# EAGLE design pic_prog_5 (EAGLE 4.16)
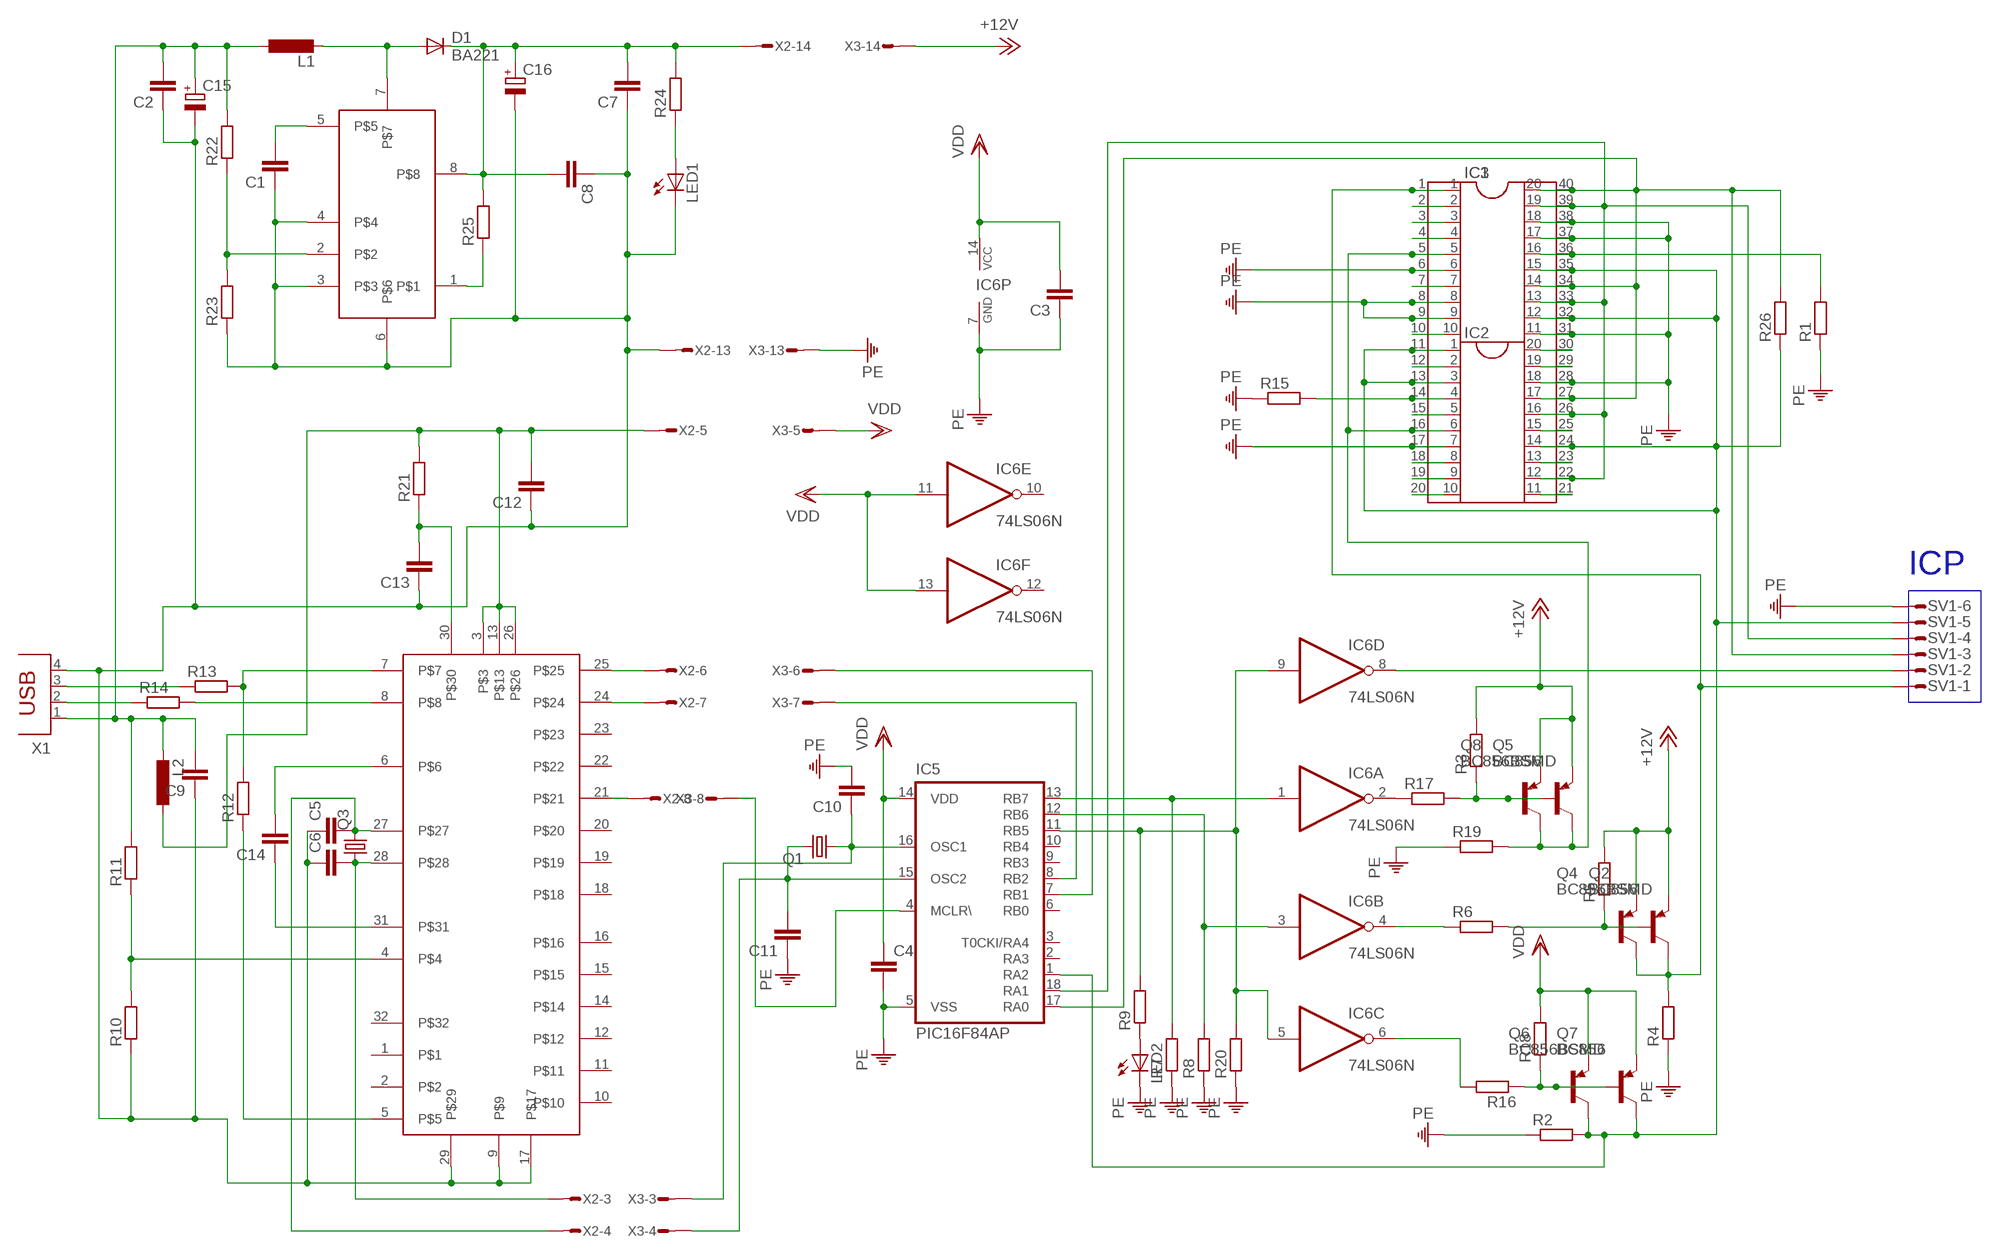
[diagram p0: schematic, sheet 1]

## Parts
C1  C-EUC1206  [C1206]
C2  C-EUC1206  [C1206]
C3  C-EU050-024X044  [C050-024X044]
C4  C-EUC1206  [C1206]
C5  C-EUC1206  [C1206]
C6  C-EUC1206  [C1206]
C7  C-EUC1206  [C1206]
C8  C-EUC1206  [C1206]
C9  C-EUC1206  [C1206]
C10  C-EUC1206  [C1206]
C11  C-EUC1206  [C1206]
C12  C-EUC1206  [C1206]
C13  C-EUC1206  [C1206]
C14  C-EUC1206  [C1206]
C15  CPOL-EUSMCD  [SMC_D]
C16  CPOL-EUSMCD  [SMC_D]
D1  BA221  [DO35-10]
IC1  DIL20  [DIL20]
IC2  DIL20  [DIL20]
IC3  DIL40  [DIL40]
IC5  PIC16F84AP  [DIL18]
IC6  74LS06N  [DIL14]
L1  L-EU2200-15.24  [2200-15.24]
L2  L-EU2200-15.24  [2200-15.24]
LED1  LED3MM  [LED3MM]
LED2  LED3MM  [LED3MM]
Q1  CRYSTALHC49U-H  [HC49U-H]
Q2  BC856  [TO92L]
Q3  CRYSTALHC49U-H  [HC49U-H]
Q4  BC856BSMD  [SOT23-BEC]
Q5  BC856  [TO92L]
Q6  BC856BSMD  [SOT23-BEC]
Q7  BC856  [TO92L]
Q8  BC856BSMD  [SOT23-BEC]
R1  R-EU_0207/10  [0207/10]
R2  R-EU_0207/10  [0207/10]
R3  R-EU_0207/10  [0207/10]
R4  R-EU_0207/10  [0207/10]
R5  R-EU_0207/10  [0207/10]
R6  R-EU_0207/10  [0207/10]
R7  R-EU_0207/10  [0207/10]
R8  R-EU_0207/10  [0207/10]
R9  R-EU_0207/10  [0207/10]
R10  R-EU_R1206  [R1206]
R11  R-EU_R1206  [R1206]
R12  R-EU_R1206  [R1206]
R13  R-EU_R1206  [R1206]
R14  R-EU_R1206  [R1206]
R15  R-EU_0207/10  [0207/10]
R16  R-EU_0207/10  [0207/10]
R17  R-EU_0207/10  [0207/10]
R18  R-EU_0207/10  [0207/10]
R19  R-EU_0207/10  [0207/10]
R20  R-EU_0207/10  [0207/10]
R21  R-EU_R1206  [R1206]
R22  R-EU_R1206  [R1206]
R23  R-EU_R1206  [R1206]
R24  R-EU_R1206  [R1206]
R25  R-EU_R1206  [R1206]
R26  R-EU_0207/10  [0207/10]
SV1  MT6-6Y.  [6_1]
U$1  FT232  [TQFP32-08]
U$2  MAX761  [DIL08]
X1  PN61729  [PN61729]
X2  MICROMATCH-20/  [PLS]
X3  MICROMATCH-20\\  [PBS]

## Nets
+12V: Q2.1(E) Q4.E Q5.1(E) Q8.E R3.2 R5.2 X3.P$14
N$1: IC1.1 IC3.1 Q2.3(C) Q4.C R4.2 SV1.P$1
N$2: IC1.2 IC3.2
N$3: IC1.3 IC3.3
N$4: IC1.4 IC3.4
N$5: C1.2 U$2.5
N$6: IC6.8(D:O) SV1.P$2
N$7: IC1.7 IC3.7
N$8: C11.2 IC5.15(OSC2) Q1.2 X3.P$4
N$9: R22.1 R23.2 U$2.2
N$10: IC1.10 IC3.10
N$12: IC2.2 IC3.12
N$13: IC5.4(MCLR\) X3.P$8
N$14: IC2.4 IC3.14 R15.2
N$15: IC2.5 IC3.15
N$16: C2.2 C9.2 C15.+ L1.1 L2.2 R11.2 R22.2 X1.1
N$18: IC2.8 IC3.18
N$19: IC2.9 IC3.19
N$20: IC2.10 IC3.20
N$21: IC2.11 IC3.21
N$22: IC1.13 IC1.19 IC2.12 IC2.16 IC3.22 IC3.26 IC3.33 IC3.39 IC5.18(RA1) SV1.P$4
N$23: IC2.13 IC3.23
N$24: IC1.12 IC1.15 IC2.1 IC2.3 IC2.14 IC3.11 IC3.13 IC3.24 IC3.32 IC3.35 IC5.1(RA2) Q6.C Q7.3(C) R2.2 R26.1 SV1.P$5
N$25: IC2.15 IC3.25
N$26: IC1.16 IC3.36 R1.2
N$29: IC2.19 IC3.29
N$30: IC2.20 IC3.30
N$31: D1.A L1.2 U$2.7
N$32: C10.1 IC5.16(OSC1) Q1.1 X3.P$3
N$33: IC1.14 IC1.20 IC2.17 IC3.27 IC3.34 IC3.40 IC5.17(RA0) R26.2 SV1.P$3
N$34: C7.2 C8.2 C16.+ D1.C R24.2 R25.2 U$2.8 X2.P$14
N$35: LED1.A R24.1
N$36: C12.2 L2.1 R21.2 U$1.3 U$1.13 U$1.26 X2.P$5
N$37: R25.1 U$2.1
N$38: U$1.25 X2.P$6
N$39: U$1.21 X2.P$8
N$40: U$1.24 X2.P$7
N$41: C14.2 U$1.6
N$42: C14.1 U$1.31
N$43: R14.1 X1.2
N$44: R14.2 U$1.8
N$45: R13.1 X1.3
N$46: R12.2 R13.2 U$1.7
N$47: R12.1 U$1.5
N$48: C6.2 Q3.1 U$1.28 X2.P$3
N$49: R10.2 R11.1 U$1.4
N$50: C1.1 C2.1 C5.1 C6.1 C7.1 C8.1 C9.1 C12.1 C13.1 C15.- C16.- LED1.K(C) R10.1 R23.1 U$1.9 U$1.17 U$1.29 U$2.3 U$2.4 U$2.6 X1.4 X2.P$13
N$51: C13.2 R21.1 U$1.30
N$52: IC5.7(RB1) X3.P$6
N$53: IC5.8(RB2) X3.P$7
N$56: Q6.B Q7.2(B) R16.1 R18.1
N$58: IC5.11(RB5) IC6.5(C:I) IC6.9(D:I) R9.2 R20.2
N$59: LED2.A R9.1
N$60: IC5.12(RB6) IC6.3(B:I) R8.2
N$61: IC5.13(RB7) IC6.1(A:I) R7.2
N$62: IC6.6(C:O) R16.2
N$63: IC6.2(A:O) R17.1
N$64: Q5.2(B) Q8.B R3.1 R17.2
N$66: IC1.5 IC2.6 IC3.5 IC3.16 Q5.3(C) Q8.C R19.2
N$67: IC6.4(B:O) R6.1
N$68: Q2.2(B) Q4.B R5.1 R6.2
N$69: C5.2 Q3.2 U$1.27 X2.P$4
PE: C3.1 C4.2 C10.2 C11.1 IC1.6 IC1.8 IC1.9 IC1.11 IC1.17 IC1.18 IC2.7 IC2.18 IC3.6 IC3.8 IC3.9 IC3.17 IC3.28 IC3.31 IC3.37 IC3.38 IC5.5(VSS) IC6.7(P:GND) LED2.K(C) R1.1 R2.1 R4.1 R7.1 R8.1 R15.1 R19.1 R20.1 SV1.P$6 X3.P$13
VDD: C3.2 C4.1 IC5.14(VDD) IC6.11(E:I) IC6.13(F:I) IC6.14(P:VCC) Q6.E Q7.1(E) R18.2 X3.P$5
Unconnected: IC5.2(RA3) IC5.3(T0CKI/RA4) IC5.6(RB0) IC5.9(RB3) IC5.10(RB4) IC6.10(E:O) IC6.12(F:O) U$1.1 U$1.2 U$1.10 U$1.11 U$1.12 U$1.14 U$1.15 U$1.16 U$1.18 U$1.19 U$1.20 U$1.22 U$1.23 U$1.32 X2.P$1 X2.P$2 X2.P$9 X2.P$10 X2.P$11 X2.P$12 X2.P$15 X2.P$16 X2.P$17 X2.P$18 X2.P$19 X2.P$20 X3.P$1 X3.P$2 X3.P$9 X3.P$10 X3.P$11 X3.P$12 X3.P$15 X3.P$16 X3.P$17 X3.P$18 X3.P$19 X3.P$20

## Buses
B$1

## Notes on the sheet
- ICP

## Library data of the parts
C1-C14 = rcl:C-EU: CAPACITOR, European symbol
C15 C16 = rcl:CPOL-EU: POLARIZED CAPACITOR, European symbol
D1 = diode:BA221: DIODE
IC1 IC2 = dil:DIL20: SOCKET DIL20
IC3 = dil:DIL40: SOCKET DIL40
IC5 = microchip:PIC16F8*: MICROCONTROLLER 8-Bit PIC16F8X Family - CMOS Flash/EEPROM Pin Compatible : PIC16F83, PIC16CR83, PIC16F84A, PIC16CR84 see also PIC16C*
IC6 = 74xx-eu:74*06: Hex INVERTER, open collector high-voltage output
L1 L2 = rcl:L-EU: INDUCTOR, European symbol
LED1 LED2 = led:LED: LED
Q1 Q3 = crystal:CRYSTAL: CRYSTAL
Q2 Q4-Q8 = transistor-pnp:BC856*: PNP Transistror
R1-R26 = rcl:R-EU_: RESISTOR, European symbol
SV1 = con-amp-mt:MT6-6Y: AMP MT6 CONNECTOR
U$1 = atmel:FT232
U$2 = maxim:MAX761
X1 = con-berg:PN61729: BERG USB connector
X2 X3 = con-amp-micromatch:MICROMATCH-20: MicroMaTch 20 9-215464-0 / 2-215464-0 Drawing Number C-215464 DDEController.pdf

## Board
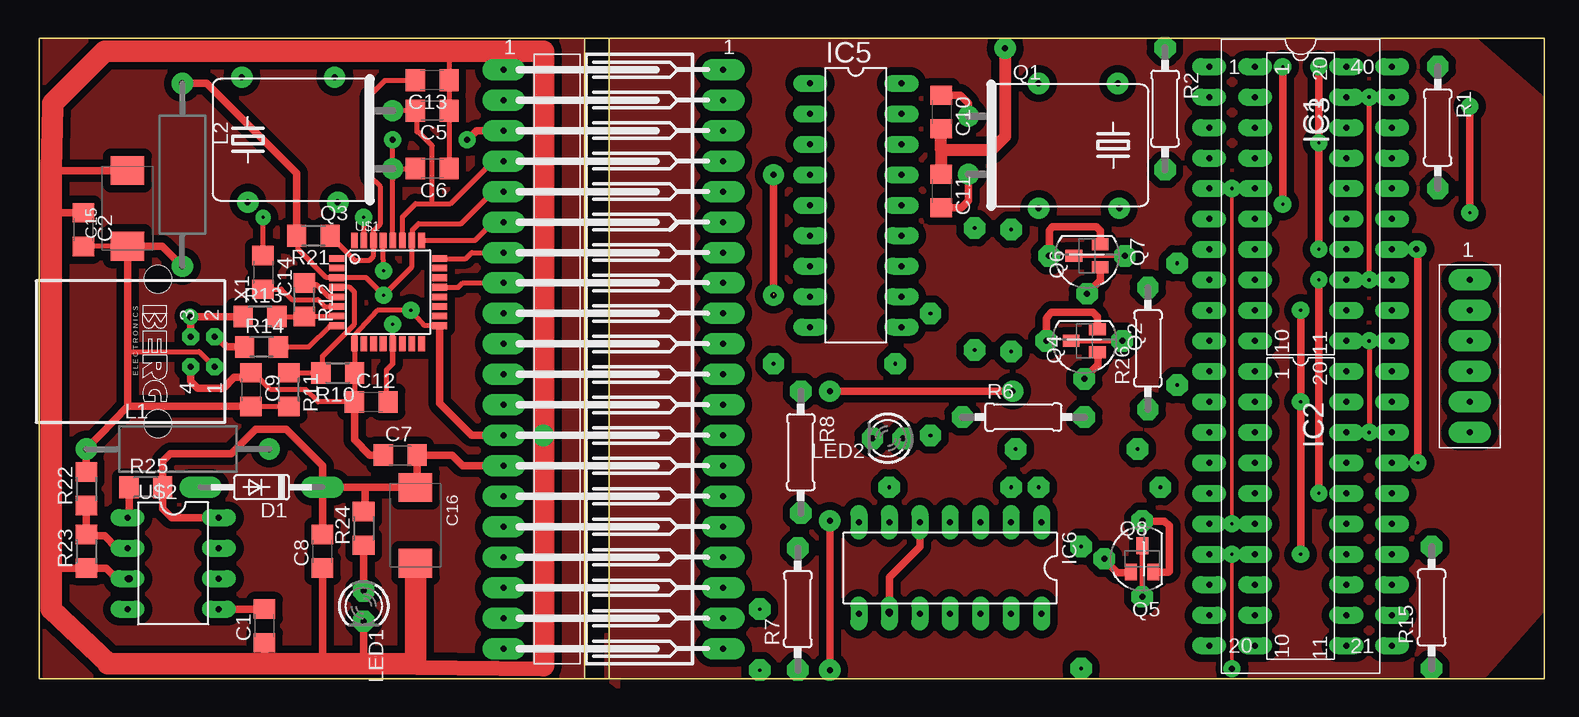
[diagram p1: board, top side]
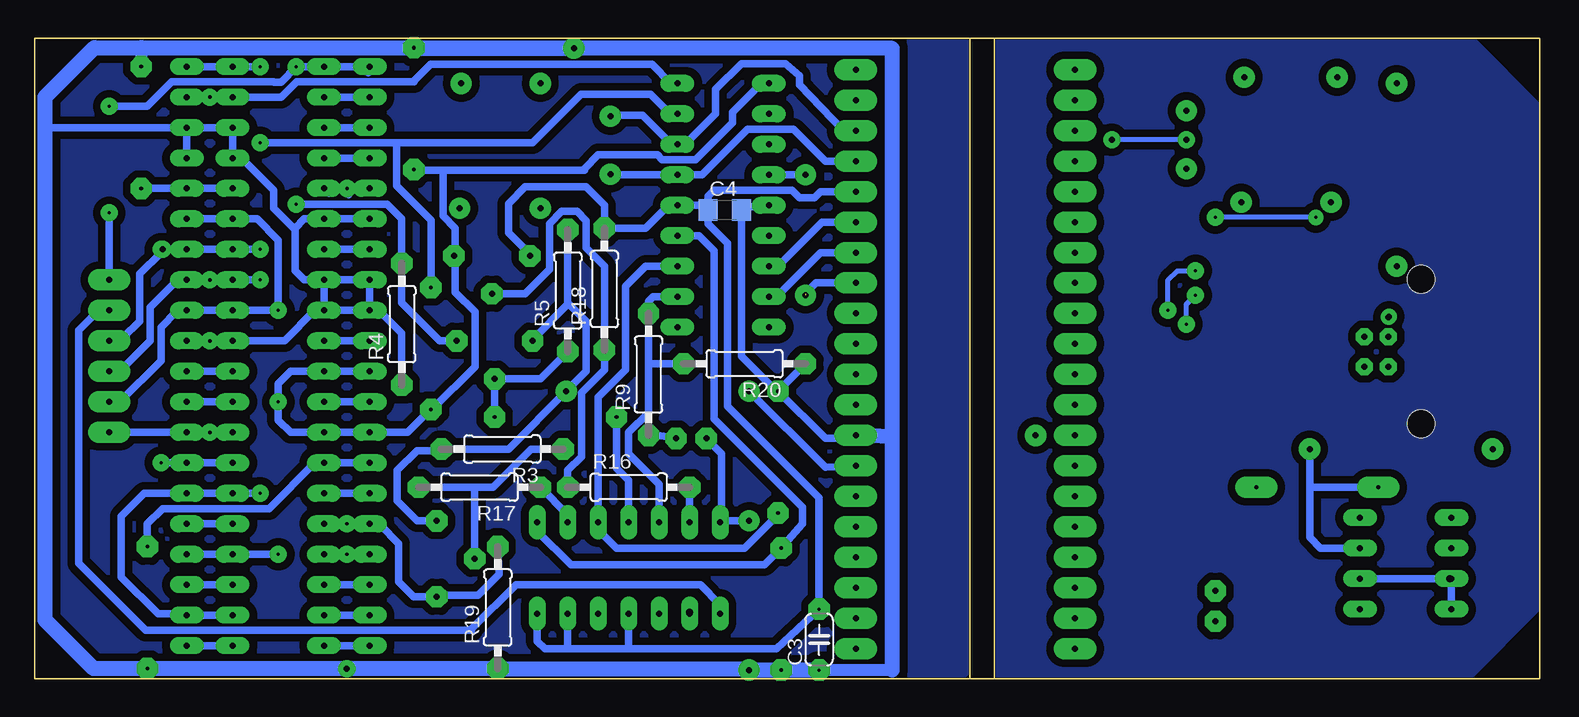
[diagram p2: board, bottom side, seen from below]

Size 125.46 x 53.39 mm. Coordinates in mm from the lower left corner, seen from the top.
Outline: 45.46,53.3 45.46,0.09
Outline: 47.49,0.09 47.49,53.3
Outline: 0,0 125.46,0 125.46,53.39 0,53.39 0,0
Copper layers (1*16): Top 0.035mm / dielectric 1.5mm / Bottom 0.035mm
Design rules "default": minimum track width 10mil, minimum drill 1mil, track to track 25mil, track to pad 25mil, pad to pad 25mil, via to via 8mil, smd to smd 8mil, copper to edge 1mil, drill to drill 10mil, minimum pad ring 10mil, minimum via ring 8mil, stop-mask expansion 4mil, vias tented up to drill 0mil, thermal gap 10mil

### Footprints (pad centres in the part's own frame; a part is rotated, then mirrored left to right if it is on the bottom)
C1206 = smd 1.6 x 1.8: 1 -1.4,0; 2 1.4,0
C050-024X044 = drill 0.254 pad 1.778 octagon: 1 -2.54,0; 2 2.54,0
SMC_D = smd 2.4 x 2.8: + -3.15,0; - 3.15,0
DO35-10 = drill 0.305 pad 1.778 long: A 5.08,0; C -5.08,0
DIL20 = drill 0.5 pad 1.422 long: 1 -11.43,-3.81; 2 -8.89,-3.81; 3 -6.35,-3.81; 4 -3.81,-3.81; 5 -1.27,-3.81; 6 1.27,-3.81; 7 3.81,-3.81; 8 6.35,-3.81; 9 8.89,-3.81; 10 11.43,-3.81; 11 11.43,3.81; 12 8.89,3.81; 13 6.35,3.81; 14 3.81,3.81; 15 1.27,3.81; 16 -1.27,3.81; 17 -3.81,3.81; 18 -6.35,3.81; 19 -8.89,3.81; 20 -11.43,3.81
DIL40 = drill 0.5 pad 1.422 long: 1 -24.13,-7.62; 2 -21.59,-7.62; 3 -19.05,-7.62; 4 -16.51,-7.62; 5 -13.97,-7.62; 6 -11.43,-7.62; 7 -8.89,-7.62; 8 -6.35,-7.62; 9 -3.81,-7.62; 10 -1.27,-7.62; 11 1.27,-7.62; 12 3.81,-7.62; 13 6.35,-7.62; 14 8.89,-7.62; 15 11.43,-7.62; 16 13.97,-7.62; 17 16.51,-7.62; 18 19.05,-7.62; 19 21.59,-7.62; 20 24.13,-7.62; 21 24.13,7.62; 22 21.59,7.62; 23 19.05,7.62; 24 16.51,7.62; 25 13.97,7.62; 26 11.43,7.62; 27 8.89,7.62; 28 6.35,7.62; 29 3.81,7.62; 30 1.27,7.62; 31 -1.27,7.62; 32 -3.81,7.62; 33 -6.35,7.62; 34 -8.89,7.62; 35 -11.43,7.62; 36 -13.97,7.62; 37 -16.51,7.62; 38 -19.05,7.62; 39 -21.59,7.62; 40 -24.13,7.62
DIL18 = drill 0.5 pad 1.422 long: 1 -10.16,-3.81; 2 -7.62,-3.81; 3 -5.08,-3.81; 4 -2.54,-3.81; 5 0,-3.81; 6 2.54,-3.81; 7 5.08,-3.81; 8 7.62,-3.81; 9 10.16,-3.81; 10 10.16,3.81; 11 7.62,3.81; 12 5.08,3.81; 13 2.54,3.81; 14 0,3.81; 15 -2.54,3.81; 16 -5.08,3.81; 17 -7.62,3.81; 18 -10.16,3.81
DIL14 = drill 0.5 pad 1.422 long: 1 -7.62,-3.81; 2 -5.08,-3.81; 3 -2.54,-3.81; 4 0,-3.81; 5 2.54,-3.81; 6 5.08,-3.81; 7 7.62,-3.81; 8 7.62,3.81; 9 5.08,3.81; 10 2.54,3.81; 11 0,3.81; 12 -2.54,3.81; 13 -5.08,3.81; 14 -7.62,3.81
2200-15.24 = drill 0.5 pad 1.778 round: 1 -7.62,0; 2 7.62,0
LED3MM = drill 0.5 pad 1.778 octagon: A -1.27,0; K 1.27,0
HC49U-H = drill 0.5 pad 1.778 round: 1 -2.413,-5.08; 2 2.413,-5.08
TO92L = drill 0.5 pad 1.778 octagon: 1 0,-3.162; 2 3.162,0; 3 0,3.162
SOT23-BEC = smd 1 x 1.4: B -0.95,-1.1; C 0,1.1; E 0.95,-1.1
0207/10 = drill 0.305 pad 1.778 octagon: 1 -5.08,0; 2 5.08,0
R1206 = smd 1.6 x 1.8: 1 -1.4,0; 2 1.4,0
6_1 = drill 0.5 pad 1.778 long: P$1 0,6.35; P$2 0,3.81; P$3 0,1.27; P$4 0,-1.27; P$5 0,-3.81; P$6 0,-6.35
TQFP32-08 = smd 1.27 x 0.559: 1 -4.293,2.8; 2 -4.293,2; 3 -4.293,1.2; 4 -4.293,0.4; 5 -4.293,-0.4; 6 -4.293,-1.2; 7 -4.293,-2; 8 -4.293,-2.8; 17 4.293,-2.8; 18 4.293,-2; 19 4.293,-1.2; 20 4.293,-0.4; 21 4.293,0.4; 22 4.293,1.2; 23 4.293,2; 24 4.293,2.8 | smd 0.559 x 1.27: 9 -2.8,-4.293; 10 -2,-4.293; 11 -1.2,-4.293; 12 -0.4,-4.293; 13 0.4,-4.293; 14 1.2,-4.293; 15 2,-4.293; 16 2.8,-4.293; 25 2.8,4.293; 26 2,4.293; 27 1.2,4.293; 28 0.4,4.293; 29 -0.4,4.293; 30 -1.2,4.293; 31 -2,4.293; 32 -2.8,4.293
DIL08 = drill 0.5 pad 1.422 long: 1 -3.81,-3.81; 2 -1.27,-3.81; 3 1.27,-3.81; 4 3.81,-3.81; 5 3.81,3.81; 6 1.27,3.81; 7 -1.27,3.81; 8 -3.81,3.81
PN61729 = drill 0.5 pad 1.422 octagon: 1 1.25,4.71; 2 -1.25,4.71; 3 -1.25,2.71; 4 1.25,2.71 | hole 2.3: -6.02,0; 6.02,0
PLS = drill 0.5 pad 1.778 long: P$1 0,24.13; P$2 0,21.59; P$3 0,19.05; P$4 0,16.51; P$5 0,13.97; P$6 0,11.43; P$7 0,8.89; P$8 0,6.35; P$9 0,3.81; P$10 0,1.27; P$11 0,-1.27; P$12 0,-3.81; P$13 0,-6.35; P$14 0,-8.89; P$15 0,-11.43; P$16 0,-13.97; P$17 0,-16.51; P$18 0,-19.05; P$19 0,-21.59; P$20 0,-24.13
PBS = drill 0.5 pad 1.778 long: P$1 5.08,24.13; P$2 5.08,21.59; P$3 5.08,19.05; P$4 5.08,16.51; P$5 5.08,13.97; P$6 5.08,11.43; P$7 5.08,8.89; P$8 5.08,6.35; P$9 5.08,3.81; P$10 5.08,1.27; P$11 5.08,-1.27; P$12 5.08,-3.81; P$13 5.08,-6.35; P$14 5.08,-8.89; P$15 5.08,-11.43; P$16 5.08,-13.97; P$17 5.08,-16.51; P$18 5.08,-19.05; P$19 5.08,-21.59; P$20 5.08,-24.13

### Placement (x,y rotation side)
C1  18.79,4.41 90 top
C2  3.68,37.43 270 top
C3  60.07,3.26 90 bottom
C4  67.94,39.08 0 bottom
C5  32.76,47.33 180 top
C6  32.76,42.51 180 top
C7  30.09,18.63 0 top
C8  23.62,10.63 90 top
C9  17.65,24.09 270 top
C10  75.2,47.23 270 top
C11  75.2,40.65 270 top
C12  27.68,23.08 0 top
C13  32.76,49.87 180 top
C14  18.66,33.87 270 top
C15  7.36,39.21 90 top
C16  31.36,12.79 270 top
D1  18.54,15.96 180 top
IC1  105.15,39.59 270 top
IC2  105.15,14.19 270 top
IC3  105.15,26.89 270 top
IC5  68.07,39.46 270 top
IC6  75.94,9.23 180 top
L1  11.55,19.14 0 top
L2  11.93,42 270 top
LED1  27.05,6.06 270 top
LED2  70.73,20.03 180 top
Q1  82.55,44.46 270 top
Q2  87.12,28.16 270 top
Q3  24.38,44.92 90 top
Q4  87.12,28.16 90 top
Q5  91.94,10 180 top
Q6  87.35,35.24 90 top
Q7  87.35,35.24 270 top
Q8  91.94,10 0 top
R1  116.58,45.94 270 top
R2  93.85,47.51 270 top
R3  86.48,19.14 180 bottom
R4  94.86,29.55 90 bottom
R5  81.02,32.35 90 bottom
R6  82.04,21.81 0 top
R7  63.24,5.8 90 top
R8  63.5,18.88 270 top
R9  74.29,25.36 90 bottom
R10  24.89,25.49 180 top
R11  20.82,24.09 270 top
R12  22.09,31.59 270 top
R13  18.41,30.19 0 top
R14  18.54,27.65 0 top
R15  116.07,5.93 90 top
R16  75.94,15.96 0 bottom
R17  88.39,15.96 180 bottom
R18  77.97,32.47 90 bottom
R19  86.86,5.93 90 bottom
R20  66.29,26.25 180 bottom
R21  22.86,36.92 180 top
R22  3.93,15.84 90 top
R23  3.93,10.63 90 top
R24  27.05,12.54 90 top
R25  8.89,15.96 0 top
R26  92.43,27.52 90 top
SV1  119.25,26.89 0 top
U$1  29.08,32.22 0 top
U$2  11.17,9.61 270 top
U$3  [REPER_3]  1.27,52.16 0 top
U$4  [REPER_3]  1.27,1.23 0 top
U$5  [REPER_3]  124.2,1.23 0 top
U$6  [REPER_3]  124.2,52.16 0 top
X1  9.9,27.27 270 top
X2  38.73,26.63 0 top
X3  51.94,26.63 0 top

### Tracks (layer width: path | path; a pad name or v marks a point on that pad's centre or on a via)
+12V  (via drill 0.5 pad 1.78)
  Top 0.406: 91.94,13.04 Q5.1 92.03,13.16 92.05,13.14 | Q2.1 83.95,28.17 83.92,28.21 | 94.2,8.98 94.12,8.89
  Top 0.61: v65.91,23.97 v81.15,23.97 | 94.12,8.89 Q8.E | 94.2,8.98 94.2,12.74 93.8,13.14 92.05,13.14 | 88.26,29.3 88.34,29.22 Q4.E 88.22,30.16 87.83,30.54 84.4,30.54 84.07,30.21 84.07,30.19 83.94,30.06 83.94,28.16 Q2.1
  Bottom 0.61: 86.99,19.14 91.31,19.14 91.44,19.27 R3.2 91.69,19.14 91.82,19.01 93.59,19.01 95.25,17.36 95.25,14.82 93.58,13.16 Q5.1 | 86.99,19.14 86.86,19.14 | 81.02,31.2 80.89,31.2 79.5,29.81 79.5,25.62 v81.15,23.97 85.97,19.14 86.99,19.14 | 81.02,31.2 R5.2 | Q2.1 83.95,28.27 81.02,31.2 | X3.P$14 59.56,17.62 v65.91,23.97
N$1  (via drill 0.25 pad 1.42)
  Top 0.254: v103.65,51.02 103.7,50.97 103.65,50.91
  Top 0.406: 90.32,28.16 Q2.3 Q4.C
  Top 0.61: v119.25,47.71 v119.25,38.82 | v103.65,39.56 103.65,50.91
  Bottom 0.61: 97.66,50.51 IC3.1 IC1.1 103.55,51.02 103.6,50.97 v103.65,51.02 103.65,50.99 104.92,49.72 105.51,49.72 105.53,49.75 114.04,49.75 116.07,47.71 v119.25,47.71 | 119.25,33.49 119.38,33.36 SV1.P$1 v119.25,38.82 | 103.6,39.59 103.63,39.56 v103.65,39.56 96.08,39.56 94.86,38.34 R4.2 94.86,31.33 91.69,28.16 Q2.3
N$2
  Bottom 0.61: IC3.2 IC1.2
N$3
  Bottom 0.61: IC1.3 101.21,45.81 101.09,45.94 IC3.3
N$4
  Bottom 0.61: IC1.4 101.21,43.4 101.09,43.27 100.96,43.4 IC3.4
N$5
  Top 0.61: C1.2 | C1.2 U$2.5 | C1.2 18.92,5.68
N$6
  Bottom 0.61: SV1.P$2 119.25,30.44 120.14,30.7 121.79,29.05 121.79,9.61 116.2,4.03 89.02,4.03 89.02,4.15 85.34,7.84 69.97,7.84 68.32,6.19 IC6.8
N$7
  Bottom 0.61: IC3.7 IC1.7
N$8
  Top 0.61: 77.36,41.52 77.39,41.54 Q1.2 77.47,39.84 76.88,39.25 C11.2
  Bottom 0.61: Q1.2 77.47,42 IC5.15 69.84,42 66.03,45.81 62.23,45.81 59.56,43.14 X3.P$4
N$9
  Top 0.61: R22.1 R23.2 4.06,11.9 5.46,11.9 6.48,10.88 7.23,10.88 U$2.2
N$10
  Bottom 0.61: IC1.10 101.34,28.28 101.21,28.16 IC3.10
N$11  (via drill 0.5 pad 1.78)
  other vias: 24.63,50.13
N$12
  Bottom 0.61: IC3.12 IC2.2
N$13  (via drill 0.5 pad 1.78)  (1 unrouted)
  Top 0.61: v61.21,31.97 v61.21,42
  Bottom 0.61: IC5.4 64.13,41.87 | IC5.4 64.26,41.87 | X3.P$8 60.32,32.98 61.21,32.09 | IC5.4 64.13,42.13 | v61.21,42 IC5.4
N$14
  Bottom 0.61: IC3.14 IC2.4 102.1,18 105.91,14.19 114.8,14.19 116.07,12.92 R15.2
N$15
  Bottom 0.61: IC3.15 IC2.5
N$16
  Top 0.406: C2.2 3.68,36.16 3.78,36.05 C15.+ | R11.2 20.7,22.69 20.7,22.7 20.69,22.69 C9.2 | X1.1 14.58,26.02 13.33,27.27 7.36,27.27
  Top 0.61: R22.2 L1.1 7.36,22.7 | C9.2 7.36,22.7 | L2.2 10.26,36.05 C15.+ 7.36,27.27 7.36,22.7
N$17  (via drill 0.5 pad 1.78)
  other vias: 24.89,39.71
N$18
  Bottom 0.61: IC2.8 101.21,7.84 101.09,7.96 100.96,7.84 IC3.18
N$19
  Bottom 0.61: IC3.19 IC2.9
N$20
  Bottom 0.61: IC3.20 IC2.10
N$21
  Bottom 0.61: IC2.11 IC3.21
N$22  (via drill 0.25 pad 1.42, 0.3 pad 1.42)
  Top 0.406: v110.87,33.24 v110.87,48.48
  Top 0.61: v106.67,15.46 v106.67,33.24
  Bottom 0.61: IC2.12 IC3.22 112.9,5.42 115.18,5.42 118.23,8.47 118.23,13.55 116.33,15.46 IC3.26 | IC3.39 v110.87,48.48 IC1.19 104.9,48.48 103.63,49.75 93.9,49.75 | IC3.26 113.03,15.46 | IC3.26 IC2.16 v106.67,15.46 | v106.67,33.24 IC1.13 v110.87,33.24 IC3.33 113.53,33.24 115.82,30.95 115.82,28.16 118.36,25.62 SV1.P$4 | SV1.P$4 120.52,25.49 | SV1.P$4 120.26,25.62 | 93.9,49.75 93.85,49.75 | IC5.18 72.44,49.62 74.01,51.19 92.45,51.19 93.9,49.75
N$23
  Bottom 0.61: IC2.13 IC3.23
N$24  (via drill 0.25 pad 1.42)
  Top 0.406: Q7.3 90.51,35.23 90.47,35.19 Q6.C
  Top 0.61: v105.15,30.7 v105.15,23.08 v105.15,10.38
  Bottom 0.61: 113.03,10.38 IC3.24 IC2.14 v105.15,10.38 | IC3.11 IC2.1 104.14,25.62 105.15,24.6 v105.15,23.08 105.15,21.55 104.14,20.54 IC2.3 IC3.13 94.36,20.54 92.45,22.44 R26.1 92.32,22.44 88.77,26 88.77,30.57 90.42,32.22 90.42,35.15 Q7.3 90.42,35.33 90.42,37.55 91.44,38.57 91.44,42.38 | IC3.35 113.03,38.32 | IC3.35 IC1.15 | IC3.35 106.93,38.32 105.15,36.54 v105.15,30.7 IC1.12 IC3.32 113.66,30.7 113.66,30.57 114.93,29.3 114.93,26.51 118.36,23.08 SV1.P$5 119.38,23.2 | R2.2 93.21,42.38 91.44,42.38 | 91.44,42.38 79.62,42.38 79.62,42.51 78.48,43.65 73.53,43.65 73.15,43.27 70.35,43.27 67.31,46.32 67.31,47.21 64.89,49.62 IC5.1
N$25
  Bottom 0.61: 112.9,12.92 IC3.25 IC2.15
N$26
  Bottom 0.61: IC1.16 IC3.36 116.33,40.86 116.45,40.73 R1.2
N$27  (via drill 0.5 pad 1.78)
  other vias: 17.39,39.71
N$28  (via drill 0.5 pad 1.78)
  other vias: 16.89,50.13
N$29
  Bottom 0.61: IC2.19 IC3.29
N$30
  Bottom 0.61: 112.9,25.62 IC3.30 | IC2.20 112.9,25.62 | 112.9,25.62 113.03,25.74
N$31
  Bottom 0.61: 19.17,15.96 L1.2 | 19.17,15.96 D1.A | U$2.7 18.28,10.88 19.17,11.77 19.17,15.96
N$32
  Top 0.61: 77.41,46.29 77.47,46.34 Q1.1 77.54,46.37 | C10.1 76.8,48.63 77.47,47.97 77.47,46.44 77.54,46.37 | 77.54,46.37 77.59,46.32
  Bottom 0.61: IC5.16 72.54,44.54 | IC5.16 72.38,44.54 74.8,46.95 77.39,46.95 Q1.1 | IC5.16 71.75,44.41 71.37,44.41 68.7,47.08 68.7,49.11 66.54,51.27 62.86,51.27 61.72,50.25 61.72,49.49 58.03,45.68 X3.P$3
N$33  (via drill 0.25 pad 1.42, 0.5 pad 1.42)
  Top 0.254: v114.8,35.78 v114.93,35.78
  Top 0.61: v106.67,51.02 v106.67,44.67 v106.67,35.78 | v114.93,35.78 v114.93,18
  Bottom 0.61: v106.67,44.67 106.29,44.54 106.17,44.67 95.42,44.67 | v106.67,51.02 IC1.20 IC3.40 | IC3.27 112.9,18 | IC3.27 IC2.17 | v106.67,35.78 IC1.14 IC3.34 v114.8,35.78 | v114.93,18 IC3.27 | v114.93,35.78 114.93,35.52 116.71,33.74 116.71,29.81 118.11,28.41 118.11,28.42 118.11,28.51 | SV1.P$3 120.39,28.28 118.11,28.51 | 118.11,28.51 117.85,28.54 | R26.2 92.43,38.21 95.3,41.09 95.3,44.51 95.32,44.54 95.37,44.54 95.37,44.59 95.42,44.64 95.42,44.67 | IC5.17 72.49,47.08 74.11,48.71 79.9,48.71 83.94,44.67 87.62,44.67 | 87.62,44.67 95.42,44.67 | 87.62,44.67 87.37,44.67
N$34
  Top 0.61: D1.C 23.62,17.74 20.57,20.79 18.03,20.79 16,18.76 10.92,18.76 10.29,18.13 R25.2 | D1.C 27.17,15.96 | C8.2 D1.C | R25.2 10.29,15.84 10.28,15.84 | R25.2 10.29,14.18 11.04,13.42 14.85,13.42 14.98,13.55 U$2.8 | R24.2 27.17,13.94 27.17,15.96 | 31.49,15.96 31.49,15.94 C16.+ | 27.17,15.96 31.49,15.96 | 31.49,15.96 C7.2 34.41,18.63 35.3,17.74 X2.P$14
N$35
  Top 0.61: LED1.A R24.1
N$36  (via drill 0.25 pad 1.42)
  Top 0.406: U$1.13 29.48,26.27 28.95,25.74 28.95,23.71 | U$1.13 29.48,29.53 v29.46,29.55 | U$1.3 24.82,33.42 | U$1.3 27.24,33.42 v28.7,31.97 31.08,34.35 U$1.26 31.11,36.55 31.11,37.43 31.62,37.94 35.17,37.94 37.84,40.6 X2.P$5 38.98,40.6 | 24.69,33.42 24.63,33.36 | U$1.3 24.69,33.42 | 24.69,33.42 23.94,33.42 21.59,35.78 21.59,36.92 R21.2 | U$1.13 29.48,26.25
  Top 0.61: 28.95,23.71 29.08,23.58 C12.2 | R21.2 21.46,38.95 21.46,42.13 13.96,49.62 L2.1
  Bottom 0.406: v28.7,31.97 29.46,31.2 v29.46,29.55
N$37
  Top 0.61: U$2.1 7.49,13.42 7.49,13.43 R25.1
N$38
  Top 0.406: X2.P$6 37.84,38.06 36.32,36.54 31.87,36.54 U$1.25
N$39
  Top 0.406: U$1.21 34.94,32.62 35.3,32.98 X2.P$8
N$40
  Top 0.406: U$1.24 35.56,35.02 36.06,35.52 40.13,35.52 40.25,35.65 X2.P$7
N$41
  Top 0.406: U$1.6 23.8,31.02 23.24,31.59 21.08,31.59 20.19,32.47 18.79,32.47 C14.2
N$42  (via drill 0.25 pad 1.27, 0.25 pad 1.42)
  Top 0.406: C14.1 v18.66,38.44 | U$1.31 27.05,36.54 v27.05,38.44
  Bottom 0.406: v18.66,38.44 v27.05,38.44
N$43
  Top 0.61: X1.2 14.75,28.52 15.62,27.65 R14.1
N$44
  Top 0.406: U$1.8 24.25,29.42 22.47,27.65 R14.2
N$45  (via drill 0.5 pad 1.27)
  Top 0.61: X1.3 v12.61,30.15 | R13.1 | v12.57,30.19 R13.1 | R13.1 17.14,30.06
  Bottom 0.61: v12.61,30.15 v12.57,30.19
N$46
  Top 0.406: U$1.7 22.25,30.22 22.22,30.19 R12.2 20.06,30.19 R13.2
N$47
  Top 0.406: U$1.5 24.14,31.82 23.11,32.86 22.22,32.86 R12.1
N$48  (via drill 0.5 pad 1.42)
  Top 0.406: Q3.1 29.46,41.62 29.48,41.6 U$1.28 | Q3.1 C6.2 | Q3.1 v29.46,44.92
  Top 0.61: X2.P$3 36.44,45.68 v35.68,44.92
  Bottom 0.406: v29.46,44.92 v35.68,44.92
N$49
  Top 0.406: U$1.4 25.88,32.62 26.28,32.22 26.28,29.55 23.62,26.89 23.62,25.62 R10.2 R11.1
N$50  (via drill 0.25 pad 1.42, 0.5 pad 1.78, 0.6)
  Top 0.406: 32.13,29.42 U$1.17 33.27,29.42 33.27,29.43 32.13,29.43 v30.98,30.7 28.19,30.7 26.28,28.66 U$1.9 R10.1 C12.1 | U$1.29 28.68,34.91 28.7,34.89 v28.7,34 28.68,34.02 | 1.01,42.38 1.27,42.38 1.29,42.36 | C12.1 | C12.1 23.24,23.08 22.22,24.09 19.3,24.09 18.03,25.36 17.78,25.36 | C6.1 C5.1 34.16,49.74 34.16,49.75 C13.1 34.16,51.65 34.16,52.29
  Top 0.61: U$2.4 7.36,5.68 | C2.1 1.01,38.83 1.01,38.82 | C9.1 17.65,25.36 17.52,25.23 | 17.78,25.36 C9.1 | 1.29,42.36 C15.- | 18.79,1.23 C1.1 | 29.46,1.23 29.46,1.1 27.05,1.23 LED1.K | C8.1 23.62,1.23 | 1.01,9.11 1.01,9.23 R23.1 5.59,9.23 6.47,8.34 v7.49,8.34 U$2.3 | X1.4 12.61,24.81 13.2,24.22 15.36,24.22 16.25,25.11 17.52,25.11 17.65,25.23 C9.1 | U$1.17 33.37,29.2 33.4,29.17 33.4,22.95 36.06,20.28 X2.P$13 v42.03,20.28 | C12.1 26.28,19.9 27.55,18.63 C7.1 | 41.78,0.85 42.03,1.1
  Top 1.27: 31.36,1.23 31.36,0.98 41.78,0.85
  Top 1.778: 18.92,1.23 23.62,1.23 27.05,1.23 29.46,1.23 31.36,1.23 C16.- | 42.03,1.1 v42.03,20.28 42.03,52.29 34.16,52.29 5.46,52.29 1.14,47.97 1.14,47.71 1.01,42.38 1.01,38.82 1.01,9.11 1.01,5.8 5.8,1.25 | 18.92,1.23 18.79,1.23 | 18.92,1.23 5.71,1.23
  Bottom 0.406: v28.7,34 30.22,34 30.98,33.24 v30.98,30.7
  Bottom 0.61: v7.49,8.34 U$2.6 | U$2.3 U$2.4
N$51
  Top 0.406: R21.1 26.29,34.89 27.55,34.89 27.88,35.21 U$1.30 27.88,37.37 28.44,37.94 28.44,40.98 27.55,41.87 27.55,48.6 28.82,49.87 C13.2
N$52
  Bottom 0.61: 64.31,34.38 IC5.7 63.5,34.38 59.81,38.06 X3.P$6
N$53
  Bottom 0.61: X3.P$7 59.94,35.52 63.62,31.84 IC5.8
N$54  (via drill 0.5 pad 1.78)
  other vias: 83.31,39.21
N$55  (via drill 0.5 pad 1.78)
  other vias: 90.04,39.21
N$56
  Top 0.61: Q7.2 87.35,32.09 88.45,33.19 Q6.B
  Bottom 0.61: 81.02,16.09 R16.1 81.02,17.36 79.88,18.5 79.88,23.84 77.97,25.74 R18.1 77.97,34.38 79.5,35.9 79.5,38.19 80.26,38.95 81.53,38.95 82.55,37.94 82.55,34.12 84.58,32.09 87.37,32.09 Q7.2
N$57  (via drill 0.5 pad 1.78)
  other vias: 83.31,49.62
N$58  (via drill 0.6)
  Top 0.61: v70.86,5.55 70.86,8.47 73.4,11.01 IC6.5
  Bottom 0.61: IC6.5 73.4,16.22 75.94,18.76 75.94,20.54 74.29,22.19 74.29,26.25 | 74.29,26.25 R9.2 74.29,31.46 73.91,31.84 IC5.11 | IC6.9 v70.86,5.55 | 74.29,26.25 R20.2
N$59
  Bottom 0.61: R9.1 74.29,20.41 LED2.A
N$60
  Bottom 0.61: IC6.3 78.35,13.04 78.48,12.92 | IC6.3 78.48,23.46 76.19,25.74 76.19,32.73 74.54,34.38 IC5.12 | R8.2 63.62,13.81 63.62,13.55 66.29,10.88 76.96,10.88 78.48,12.41 IC6.3
N$61
  Bottom 0.61: IC5.13 70.1,36.92 68.83,35.65 68.83,21.68 61.46,14.31 61.46,12.92 R7.2 64.64,9.49 80.77,9.49 83.56,12.28 IC6.1 83.56,13.17
N$62
  Bottom 0.61: IC6.6 R16.2
N$63
  Bottom 0.61: IC6.2 81.02,13.68 R17.1
N$64
  Top 0.406: 91.05,8.85 91.01,8.89 Q8.B | 88.77,9.97 88.78,9.98 Q5.2
  Top 0.61: 91.05,8.85 89.89,8.85 88.77,9.97
  Bottom 0.61: 93.59,15.96 R17.2 88.77,15.96 | 88.77,15.96 88.77,15.84 88.78,15.82 Q5.2 | R3.1 84.07,19.14 87.24,15.96 88.77,15.96
N$65  (via drill 0.5 pad 1.78)
  other vias: 89.91,49.62
N$66  (via drill 0.25 pad 1.42)
  Top 0.305: v99.44,12.92 v99.41,40.86
  Top 0.406: 92.06,6.83 92.07,6.82 | Q5.3 92.06,6.83 | Q8.C 91.94,6.95 92.06,6.83
  Bottom 0.61: R19.2 86.74,8.72 88.51,6.95 91.56,6.95 91.82,6.69 91.94,6.82 Q5.3 93.86,6.83 95.12,8.09 95.12,11.27 96.64,12.79 97.28,12.79 97.53,13.04 IC3.16 v99.44,12.92 IC2.6 | v99.41,40.86 99.31,40.35 | v99.41,40.86 IC3.5 | IC1.5 100.96,40.48 100.83,40.86 v99.41,40.86
N$67
  Bottom 0.61: IC6.4 75.94,16.52 76.96,17.54 R6.1
N$68
  Top 0.406: Q2.2 87.12,24.98
  Top 0.61: 88.39,27.01 88.34,27.06 Q4.B 88.34,27.1 88.26,27.01 88.26,26.15 Q2.2
  Bottom 0.61: 87.12,24.98 R6.2 | 87.12,24.98 Q2.2 | R5.1 83.31,24.98 87.12,24.98
N$69
  Top 0.406: U$1.27 30.28,38.5 31.36,39.59 32.76,39.59 | C5.2 31.24,47.33 | C5.2 Q3.2 | C5.2 31.49,47.33 31.49,45.55 31.62,45.55 32.76,44.41 32.76,39.59 | X2.P$4 37.84,43.14 34.29,39.59 32.76,39.59
N$70
  pour Bottom: 45.22,53.15 5.46,53.15 0.2,47.89 0.2,5.78 5.88,0.1 45.3,0.1 45.44,0.24 45.44,53.15 45.36,53.23 45.02,53.23
N$71
  pour Bottom: 47.98,53.12 120.45,53.11 125.26,48.31 125.26,5.09 120.4,0.24 47.99,0.24 47.79,0.44 47.79,53.09 47.85,53.15
N$72
  pour Top: 0.5,53.18 45.21,53.18 45.21,0.22 0.5,0.22
N$73
  pour Top: 47.57,53.07 47.29,0.03 48.26,-0.66 48.27,53.07
N$74
  pour Top: 47.35,0.3 120.56,0.34 125.45,5.88 125.47,48.2 119.63,53.3 47.63,53.3
PE  (via drill 0.25 pad 1.42, 0.3 pad 1.42, 0.5 pad 1.42, 0.5 pad 1.78)
  Top 0.305: v99.44,0.85 v99.44,10.38
  Top 0.406: v110.87,28.16 v110.87,20.54
  Top 0.61: v65.91,0.72 v65.91,13.17
  Top 1.016: C10.2 75.18,45.83 75.18,44.03 | C11.1 75.18,42.05 75.18,44.03 | 75.18,44.03 79.37,44.03 80.51,45.17 v80.51,52.54
  Bottom 0.61: IC3.38 IC3.37 | IC3.38 IC1.18 IC1.17 | IC2.18 v110.87,20.54 IC3.28 SV1.P$6 | IC3.31 v110.87,28.16 IC1.11 104.64,28.16 102.1,30.7 IC1.9 | 124.58,45.94 IC3.38 | IC1.9 97.78,30.7 | 101.21,10.38 101.34,10.25 IC2.7 101.34,10.5 101.21,10.38 | IC3.17 v99.44,10.38 101.21,10.38 | IC1.17 109.09,43.4 | IC3.6 IC1.6 102.99,38.32 103.75,37.55 103.75,37.43 | IC1.8 101.47,33.11 101.34,32.98 IC1.9 | 97.78,30.7 IC3.9 96.77,30.7 94.86,28.79 R4.1 | 97.78,30.7 97.53,30.95 IC3.8 IC1.8 | IC1.8 101.47,33.36 | IC1.17 108.2,43.4 105.53,40.73 105.53,39.21 103.75,37.43 | 103.75,37.43 103.75,34 102.99,33.24 IC1.8 | v65.91,13.17 68.19,13.17 | 68.19,13.17 IC6.7 | LED2.K 68.19,18.76 68.19,13.17 | X3.P$13 56.89,20.03 59.56,20.03 R8.1 | R8.1 63.88,24.22 66.54,26.89 66.54,39.33 | R8.1 R20.1 | v65.91,0.72 65.96,0.78 | 86.86,0.78 R19.1 | 66.54,39.33 66.54,39.46 C4.2 66.54,39.33 | IC5.5 64.38,39.33 66.54,39.33
  Bottom 1.016: 53.97,0.72 C3.1 | 116.58,52.59 R1.1
  Bottom 1.27: 86.99,1.1 R19.1 v99.44,0.85 R15.1 120.54,0.85 124.58,4.89 124.58,45.94 124.58,48.49 120.48,52.59 116.58,52.59 R2.1 93.72,52.59 93.72,52.54 v80.51,52.54 | 53.97,0.72 53.97,20.16 | 53.97,20.16 53.97,52.54 93.85,52.54 | 53.97,20.16 X3.P$13 | C3.1 R7.1 v65.91,0.72 | 65.96,0.78 86.86,0.78
VDD
  Top 0.61: 84.2,35.27 Q7.1 84.2,37.38 84.47,37.66 88.13,37.66 88.45,37.34 Q6.E
  Bottom 0.61: 83.69,5.42 IC6.14 83.56,3.14 82.93,2.5 81.02,2.5 | 75.94,2.5 IC6.11 | 81.02,2.5 IC6.13 | Q7.1 84.18,35.38 85.97,37.17 85.97,39.59 84.58,40.98 79.5,40.98 77.97,39.46 R18.2 74.54,37.55 72.64,39.46 IC5.14 69.21,39.46 69.21,39.21 C4.1 | 75.94,2.5 81.02,2.5 | 75.94,2.5 63.62,2.5 C3.2 60.07,15.08 67.69,22.7 67.69,36.28 69.34,37.94 69.34,39.21 | 69.34,39.21 C4.1 | X3.P$5 59.94,40.6 60.45,40.09 61.72,40.09 62.35,40.73 68.83,40.73 69.34,40.22 69.34,39.21 | 69.34,39.21 69.34,39.2 C4.1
